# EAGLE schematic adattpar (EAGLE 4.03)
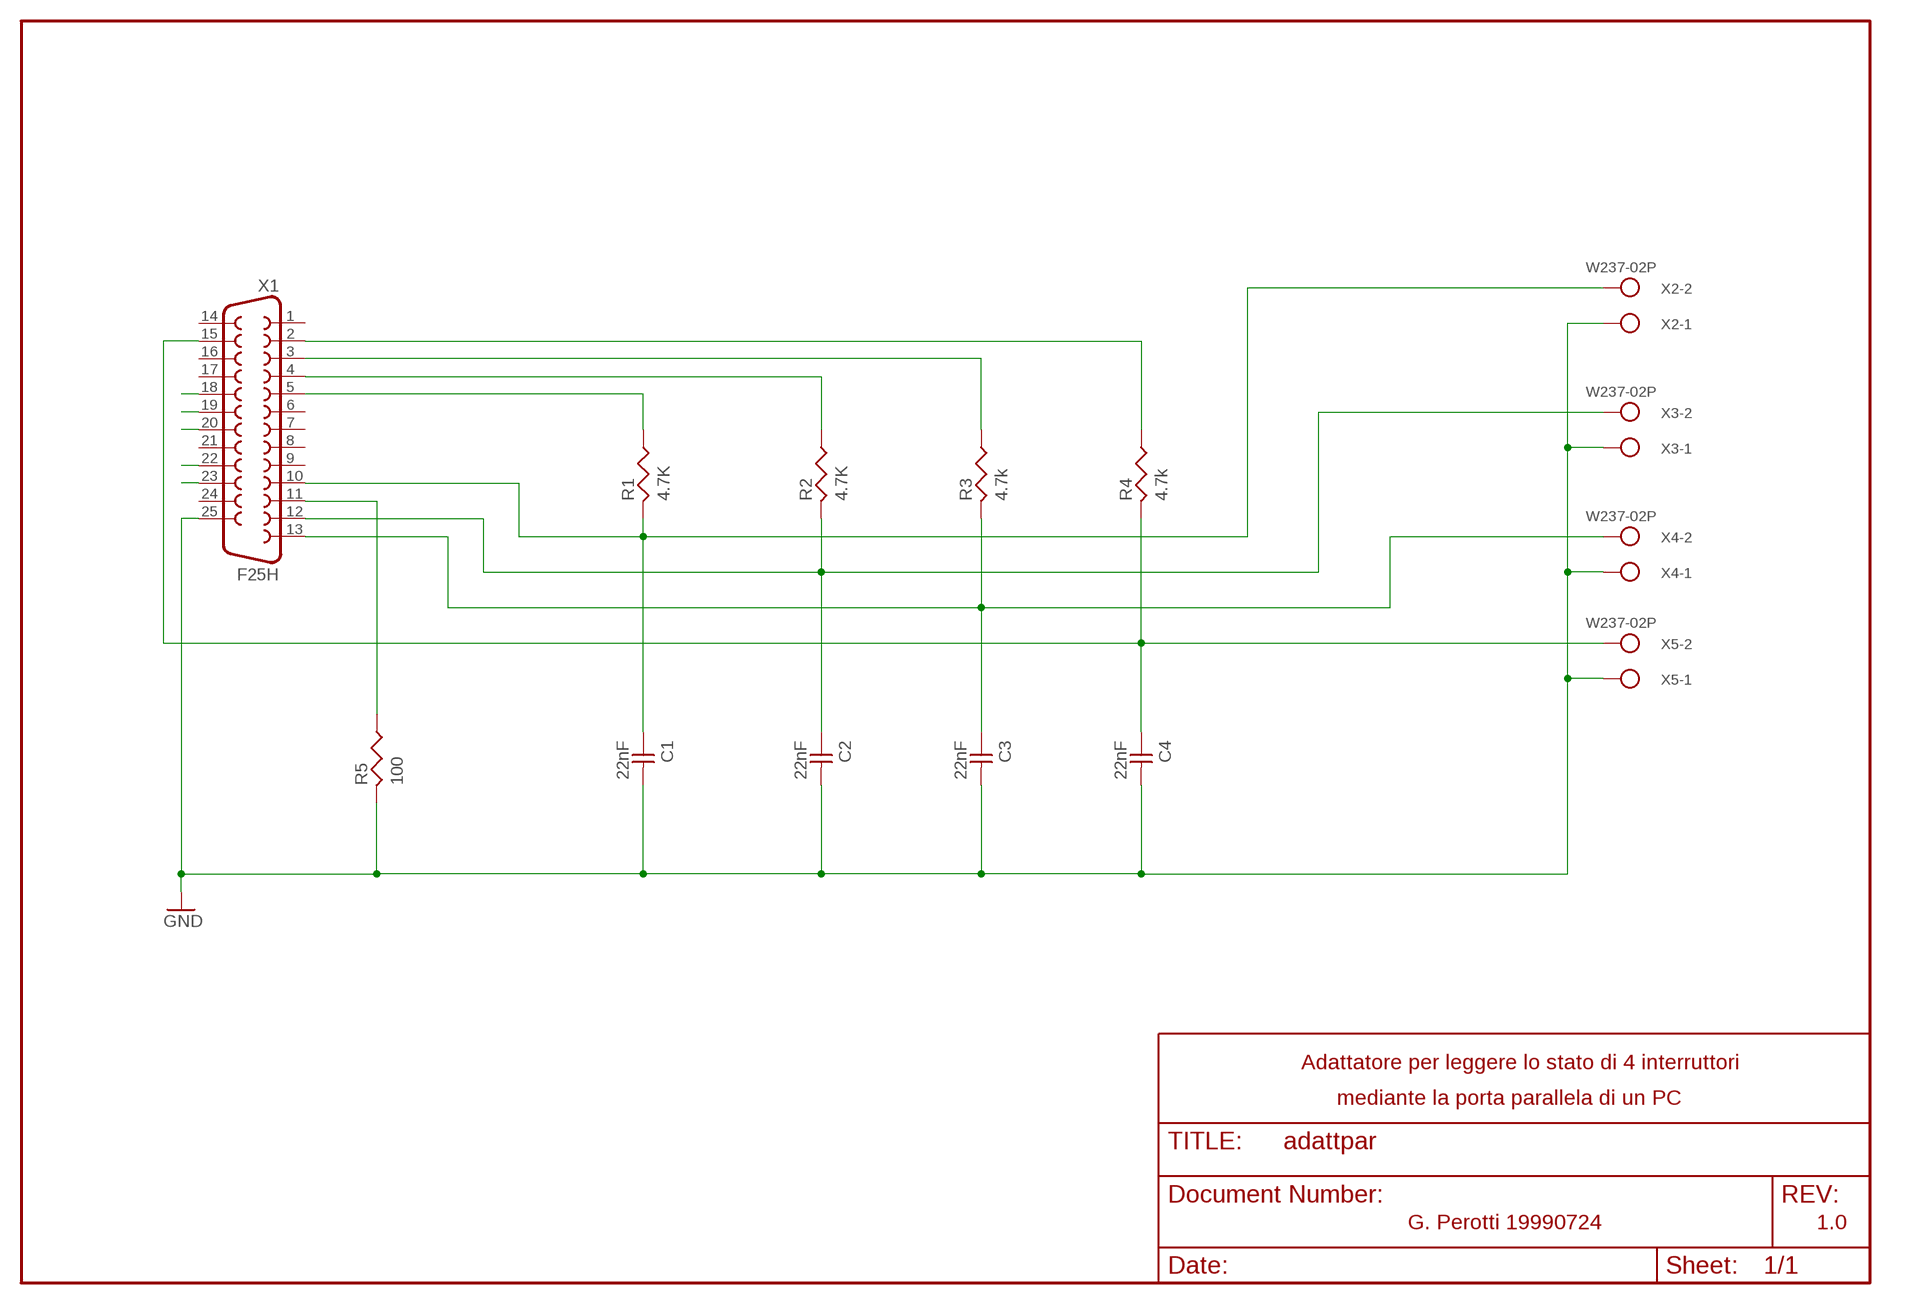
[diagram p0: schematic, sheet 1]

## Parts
C1  22nF  CAPNP-10  [C-10]
C2  22nF  CAPNP-10  [C-10]
C3  22nF  CAPNP-10  [C-10]
C4  22nF  CAPNP-10  [C-10]
R1  4.7K  RESUS-12,5  [R-12,5]
R2  4.7K  RESUS-12,5  [R-12,5]
R3  4.7k  RESUS-12,5  [R-12,5]
R4  4.7k  RESUS-12,5  [R-12,5]
R5  100  RESUS-12,5  [R-12,5]
X1  F25H  [F25H]
X2  W237-02P  [W237-132]
X3  W237-02P  [W237-132]
X4  W237-02P  [W237-132]
X5  W237-02P  [W237-132]

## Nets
GND: C1.2 C2.2 C3.2 C4.2 R5.2 X1.25 X2.1 X3.1 X4.1 X5.1
N$1: C1.1 R1.2 X1.10 X2.2
N$2: C4.1 R4.2 X1.15 X5.2
N$3: R5.1 X1.11
N$4: X1.18
N$5: R4.1 X1.2
N$6: R3.1 X1.3
N$7: R2.1 X1.4
N$8: R1.1 X1.5
N$9: X1.23
N$10: C2.1 R2.2 X1.12 X3.2
N$11: C3.1 R3.2 X1.13 X4.2
N$12: X1.22
N$14: X1.20
N$15: X1.19
Unconnected: X1.1 X1.6 X1.7 X1.8 X1.9 X1.14 X1.16 X1.17 X1.21 X1.24

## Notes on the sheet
- Adattatore per leggere lo stato di 4 interruttori
- mediante la porta parallela di un PC
- G. Perotti 19990724 | 1.0

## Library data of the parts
C1-C4 = discrete:CAPNP-10
R1-R5 = discrete:RESUS-12,5
X1 = subd:F25H
X2-X5 = wago508:W237-02P

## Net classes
0 default: width 1.27 mm, clearance 0.61 mm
